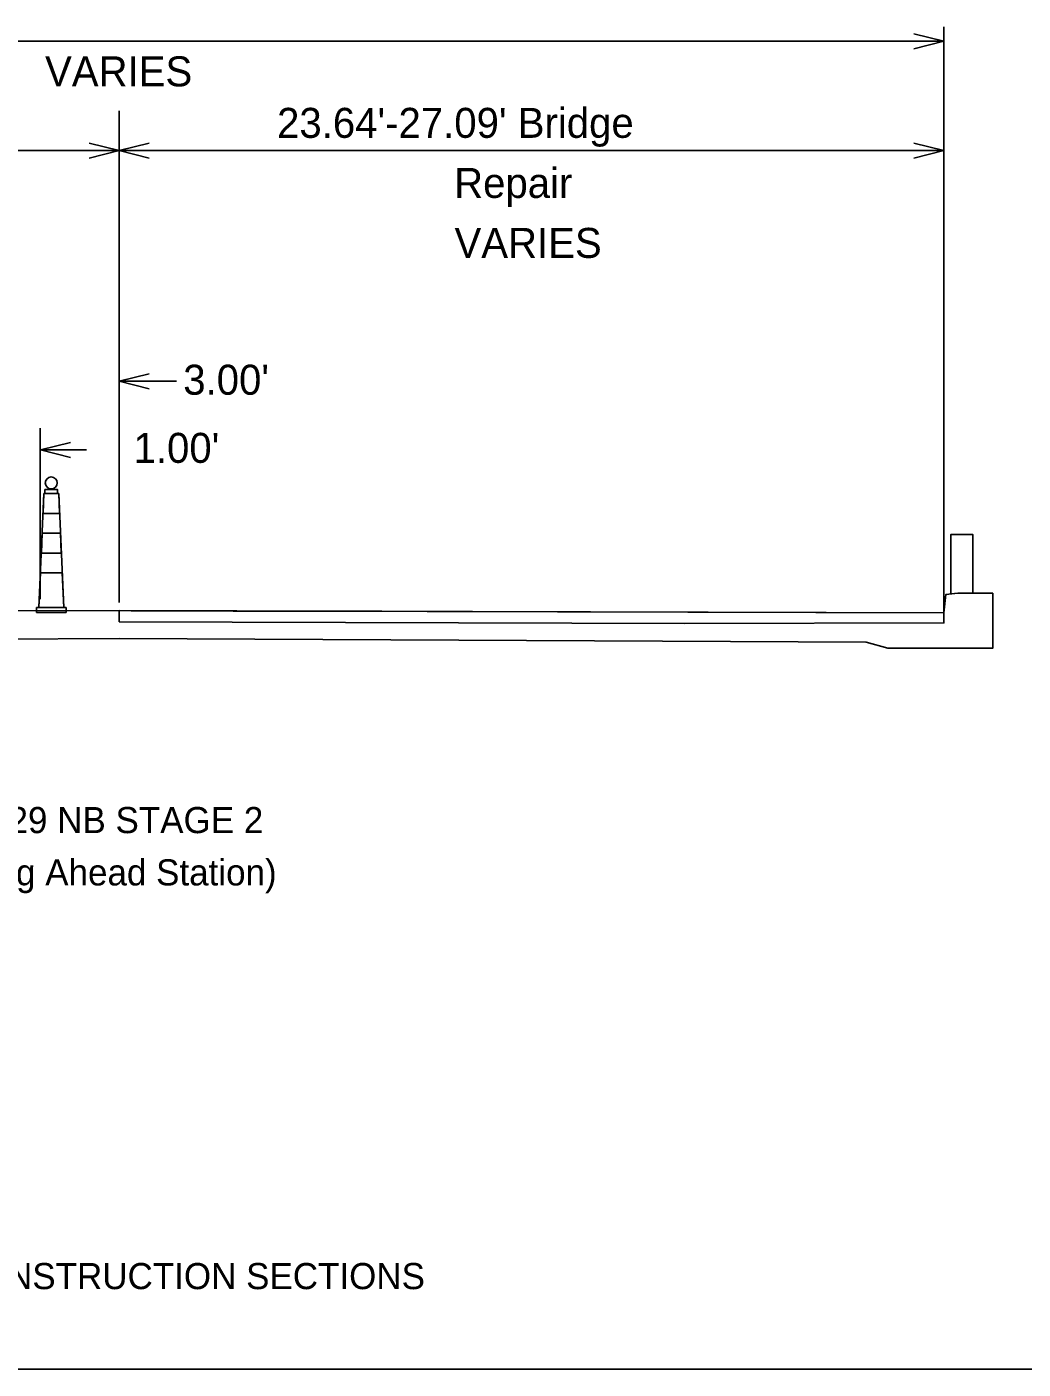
# Model space of a CAD drawing. Extents: x 8771 to 81668, y 6145 to 11018.
# Drawn here: x 11603 to 12357, y 7924 to 8940 of the extents above; entities that cross this region are included whole.
import ezdxf

# ---------------------------------------------------------------- set-up
doc = ezdxf.new("R2010")
doc.units = 0
for name, color, linetype in [('dsnCellElements', 7, 'Continuous'), ('DsnShtRevisedText', 7, 'Continuous'), ('Level 8', 7, 'Continuous'), ('SheetBorder', 7, 'Continuous'), ('ShtPlotIdentification', 7, 'Continuous')]:
    doc.layers.add(name, color=color, linetype=linetype)

msp = doc.modelspace()

# ---------------------------------------------------------------- linework, layer by layer
at = {"layer": 'dsnCellElements'}
for p, q in [((12297.1, 8496.8), (12297.1, 8940.4)), ((11048.5, 8929.5), (12297.1, 8929.5)), ((11672.8, 8504.6), (11672.8, 8876.9)), ((11048.5, 8846.8), (11672.8, 8846.8)), ((11672.8, 8846.8), (12297.1, 8846.8)), ((11672.8, 8672.1), (11716.2, 8672.1)), ((11613, 8507.1), (11613, 8636.6)), ((11648.1, 8620.1), (11613.4, 8620.1)), ((12302.3, 8511), (12307.5, 8511.6)), ((12307.5, 8511.6), (12319, 8511.6)), ((11107.3, 8474.4), (11672.8, 8477.3)), ((12238.3, 8474.4), (11672.8, 8477.3)), ((12254.5, 8469.9), (12238.3, 8474.4))]:
    msp.add_line(p, q, dxfattribs=at)
for points in [[(12274.4, 8935.2), (12297.1, 8929.5), (12274.4, 8923.8)], [(11650.1, 8852.4), (11672.8, 8846.8), (11650.1, 8841.1)], [(11695.5, 8841.1), (11672.8, 8846.8), (11695.5, 8852.4)], [(12274.4, 8852.4), (12297.1, 8846.8), (12274.4, 8841.1)], [(11695.5, 8666.4), (11672.8, 8672.1), (11695.5, 8677.8)], [(11636.1, 8614.4), (11613.4, 8620.1), (11636.1, 8625.8)], [(12319, 8511.6), (12319, 8556), (12302.3, 8556), (12302.3, 8511)], [(12334, 8511.6), (12334, 8469.9), (12254.5, 8469.9)], [(12334, 8511.6), (12307.5, 8511.6), (12298.5, 8510.6), (12297.1, 8496.8)]]:
    msp.add_lwpolyline(points, dxfattribs=at)
at = {"layer": 'DsnShtRevisedText'}
msp.add_lwpolyline([(12319, 8511.6), (12319, 8556), (12302.3, 8556), (12302.3, 8511)], dxfattribs=at)
at = {"layer": 'Level 8'}
for p, q in [((11615.9, 8587), (11612.2, 8500.7)), ((11615.9, 8587), (11615.3, 8572)), ((11627.2, 8587), (11615.9, 8587)), ((11627.2, 8587), (11615.9, 8587)), ((11630.9, 8500.7), (11627.2, 8587)), ((11627.8, 8572), (11627.2, 8587)), ((11627.8, 8572), (11615.3, 8572)), ((11615.3, 8572), (11627.8, 8572)), ((11614.6, 8557), (11614, 8542)), ((11628.5, 8557), (11614.6, 8557)), ((11628.5, 8557), (11614.6, 8557)), ((11629.1, 8542), (11628.5, 8557)), ((11629.1, 8542), (11614, 8542)), ((11614, 8542), (11629.1, 8542)), ((11613.3, 8527), (11612.2, 8500.7)), ((11629.8, 8527), (11613.3, 8527)), ((11629.8, 8527), (11613.3, 8527)), ((11630.9, 8500.7), (11629.8, 8527)), ((11632.8, 8500.7), (11610.3, 8500.7)), ((11610.3, 8500.7), (11610.3, 8497)), ((11612.2, 8500.7), (11630.9, 8500.7)), ((11632.8, 8497), (11632.8, 8500.7)), ((11632.8, 8497), (11610.3, 8497))]:
    msp.add_line(p, q, dxfattribs=at)
msp.add_lwpolyline([(11616.7, 8590), (11626.3, 8590), (11626.3, 8587), (11616.7, 8587)], close=True, dxfattribs=at)
msp.add_circle((11621.5, 8595.1), 4.5, dxfattribs=at)
at = {"layer": 'SheetBorder'}
msp.add_lwpolyline([(10132.5, 9944), (13267.5, 9944), (13267.5, 7924), (10132.5, 7924)], close=True, dxfattribs=at)
at = {"layer": 'ShtPlotIdentification'}
for p, q in [((11672.8, 8498.4), (11048.5, 8496.8)), ((11672.8, 8498.4), (12297.1, 8496.8)), ((11672.8, 8490), (11672.8, 8494.6)), ((12101.1, 8488.7), (11672.8, 8490))]:
    msp.add_line(p, q, dxfattribs=at)
for points in [[(11672.8, 8494.6), (11672.8, 8498.4), (11682, 8498.3), (11700.5, 8498.3), (11726.5, 8498.2), (11759.2, 8498.1), (11806.4, 8498), (11871.6, 8497.9), (11906.1, 8497.8), (12103.3, 8497.3)], [(12103.3, 8497.3), (12297.1, 8496.8), (12297.1, 8489.1), (12101.1, 8488.7)]]:
    msp.add_lwpolyline(points, dxfattribs=at)

# ---------------------------------------------------------------- texts
at = {"layer": 'dsnCellElements'}
for s, height, p in [('VARIES', 22.71, (11616.8, 8895.4)), ("23.64'-27.09' Bridge", 22.709, (11792.4, 8856.4)), ('Repair', 22.71, (11926.4, 8810.9)), ('VARIES', 22.71, (11926.7, 8765.5)), ("3.00'", 22.71, (11721.4, 8661.9)), ("1.00'", 22.71, (11683.8, 8610.3)), ('I-29 NB STAGE 2', 19.8, (11573, 8329.9)), ('(Looking Ahead Station)', 19.8, (11508, 8290.3)), ('TYPICAL CONSTRUCTION SECTIONS', 19.8, (11430.6, 7984.6))]:
    msp.add_text(s, height=height, dxfattribs=at).set_placement(p)

doc.saveas('drawing.dxf')
